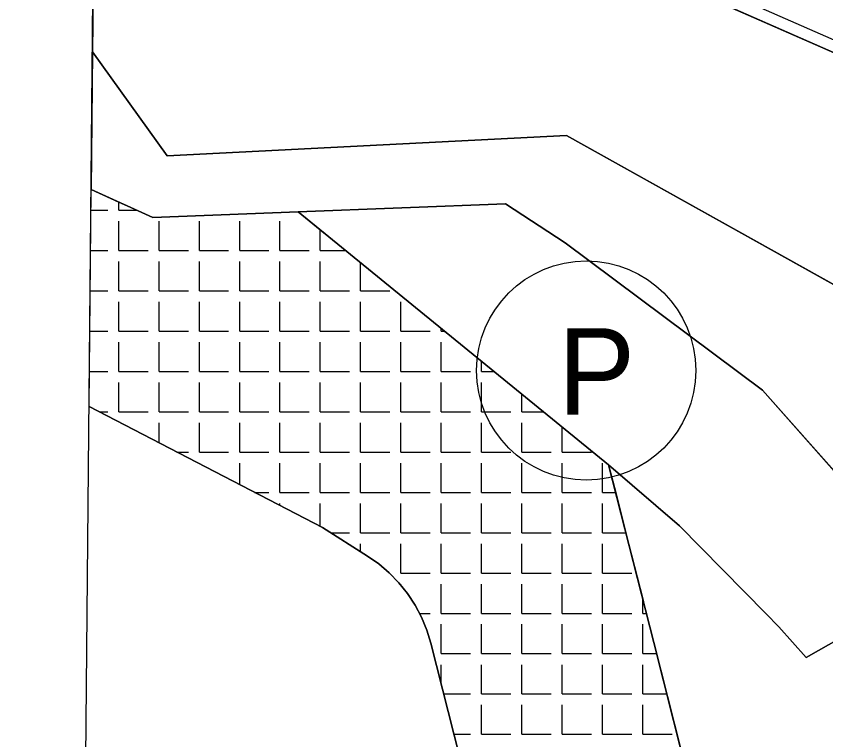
# Model space of a CAD drawing. Extents: x 427903 to 430077, y 4477233 to 4480385.
# Drawn here: x 427902.6 to 428042.9, y 4478521.2 to 4478646.6 of the extents above; entities that cross this region are included whole.
import ezdxf

# ---------------------------------------------------------------- set-up
doc = ezdxf.new("R2010")
doc.units = 0
for name, color, linetype in [('ADA', 7, 'Continuous'), ('ADAKENARI', 7, 'Continuous'), ('KALDIRIM', 7, 'Continuous'), ('KIYI', 7, 'Continuous'), ('KIYIKENARCIZGI', 7, 'Continuous'), ('LJ_SEMBOL', 7, 'Continuous'), ('PL_AYA_PARK_DINLENME', 7, 'Continuous'), ('PL_DOLGU', 7, 'Continuous'), ('PL_K_TALI_IS_MRK', 7, 'Continuous'), ('PL_KON_MEV_350', 7, 'Continuous'), ('PL_TA_K_OTOPARK', 7, 'Continuous'), ('SıNıR', 7, 'Continuous'), ('TR_KIYI', 7, 'Continuous'), ('TR_ORTAYOGUNKONUT', 7, 'Continuous'), ('TR_TALIISMERK', 7, 'Continuous')]:
    doc.layers.add(name, color=color, linetype=linetype)

msp = doc.modelspace()

# ---------------------------------------------------------------- linework, layer by layer
at = {"layer": 'ADA'}
msp.add_lwpolyline([(428005.26, 4478568.85), (428017.53, 4478558.25), (428032.49, 4478543.09), (428034.75, 4478540.79), (428039.48, 4478535.47), (428059.64, 4478546.89)], dxfattribs=at)
at = {"layer": 'ADAKENARI'}
for p, q in [((427945.65, 4478683.57), (428091.19, 4478619.67)), ((427915.79, 4478640.39), (427928.72, 4478622.38)), ((427928.72, 4478622.38), (427997.98, 4478625.89)), ((427997.98, 4478625.89), (428051.01, 4478596.31)), ((427926.24, 4478611.7), (427915.56, 4478616.56)), ((427987.4, 4478614.09), (427951.44, 4478612.68)), ((427997.71, 4478607.32), (427987.4, 4478614.09)), ((427951.44, 4478612.68), (427926.24, 4478611.7)), ((428031.92, 4478581.8), (427997.71, 4478607.32)), ((428048.79, 4478562.75), (428031.92, 4478581.8))]:
    msp.add_line(p, q, dxfattribs=at)
at = {"layer": 'KALDIRIM'}
msp.add_line((428092, 4478621.5), (427946.46, 4478685.4), dxfattribs=at)
at = {"layer": 'KIYI'}
for p, q in [((427915.2, 4478578.93), (427955.66, 4478557.97)), ((427955.66, 4478557.97), (427963.47, 4478553.04)), ((427963.47, 4478553.04), (427965.43, 4478551.67)), ((427965.43, 4478551.67), (427967.24, 4478550.12)), ((427967.24, 4478550.12), (427968.91, 4478548.4)), ((427968.91, 4478548.4), (427970.4, 4478546.54)), ((427970.4, 4478546.54), (427971.71, 4478544.54)), ((427971.71, 4478544.54), (427972.82, 4478542.43)), ((427972.82, 4478542.43), (427973.73, 4478540.22)), ((427973.73, 4478540.22), (427974.43, 4478537.94)), ((427974.43, 4478537.94), (427979.44, 4478518.13))]:
    msp.add_line(p, q, dxfattribs=at)
at = {"layer": 'KIYIKENARCIZGI'}
for p, q in [((428005.26, 4478568.85), (427951.44, 4478612.68)), ((428013.08, 4478538.04), (428005.26, 4478568.85)), ((428022.63, 4478500.39), (428013.08, 4478538.04))]:
    msp.add_line(p, q, dxfattribs=at)
at = {"layer": 'LJ_SEMBOL'}
msp.add_circle((428001.38, 4478585.19), 19, dxfattribs=at)
at = {"layer": 'PL_AYA_PARK_DINLENME'}
msp.add_lwpolyline([(428114.25, 4478313.51), (428064.87, 4478539.25), (428059.64, 4478546.89), (428039.48, 4478535.47), (428034.75, 4478540.79), (428032.49, 4478543.09), (428017.53, 4478558.25), (428005.26, 4478568.85), (428006.48, 4478564.07), (428008.25, 4478557.08), (428011.16, 4478545.62), (428011.79, 4478543.11), (428013.08, 4478538.04), (428013.56, 4478536.13), (428015.34, 4478529.14), (428018.14, 4478518.08)], dxfattribs=at)
at = {"layer": 'PL_DOLGU'}
for points in [[(427915.2, 4478578.93), (427915.56, 4478616.56)], [(427915.2, 4478578.93), (427915.56, 4478616.56)], [(427915.56, 4478616.56), (427926.24, 4478611.7), (427951.44, 4478612.68), (428005.26, 4478568.85), (428013.08, 4478538.04), (428022.63, 4478500.39), (428030.78, 4478471), (428043.19, 4478419.02), (428062.79, 4478335.7), (428065.05, 4478326.22), (428070.28, 4478297.7), (428077.59, 4478258.73), (428080.14, 4478238.03), (428083.58, 4478195.5), (428087.15, 4478152.17), (428090.62, 4478147.29), (428105.66, 4478126.11), (428131.83, 4478090.59), (428146.88, 4478022.13), (428153.28, 4477995.07), (428160.32, 4477964.05), (428161.5, 4477959.01), (428182.61, 4477892.78)], [(427915.56, 4478616.56), (427926.24, 4478611.7), (427951.44, 4478612.68), (428005.26, 4478568.85), (428013.08, 4478538.04), (428022.63, 4478500.39), (428030.78, 4478471), (428043.19, 4478419.02), (428062.79, 4478335.7), (428065.05, 4478326.22), (428070.28, 4478297.7), (428077.59, 4478258.73), (428080.14, 4478238.03), (428083.58, 4478195.5), (428087.15, 4478152.17), (428090.62, 4478147.29), (428105.66, 4478126.11), (428131.83, 4478090.59), (428146.88, 4478022.13), (428153.28, 4477995.07), (428160.32, 4477964.05), (428161.5, 4477959.01), (428182.61, 4477892.78)], [(427979.44, 4478518.13), (427974.43, 4478537.94), (427973.73, 4478540.22), (427972.82, 4478542.43), (427971.71, 4478544.54), (427970.4, 4478546.54), (427968.91, 4478548.4), (427967.24, 4478550.12), (427965.43, 4478551.67), (427963.47, 4478553.04), (427955.66, 4478557.97), (427915.2, 4478578.93)], [(427979.44, 4478518.13), (427974.43, 4478537.94), (427973.73, 4478540.22), (427972.82, 4478542.43), (427971.71, 4478544.54), (427970.4, 4478546.54), (427968.91, 4478548.4), (427967.24, 4478550.12), (427965.43, 4478551.67), (427963.47, 4478553.04), (427955.66, 4478557.97), (427915.2, 4478578.93)]]:
    msp.add_lwpolyline(points, dxfattribs=at)
at = {"layer": 'PL_K_TALI_IS_MRK'}
for points in [[(427915.79, 4478640.39), (427915.56, 4478616.56)], [(427920.35, 4478614.38), (427923.47, 4478612.96), (427926.24, 4478611.7), (427951.44, 4478612.68), (427987.4, 4478614.09), (427997.71, 4478607.32), (428031.92, 4478581.8), (428048.79, 4478562.75), (428050.54, 4478560.19), (428080.55, 4478566.83), (428080.72, 4478566.87), (428051.01, 4478596.31), (427997.98, 4478625.89), (427928.72, 4478622.38), (427915.79, 4478640.39)], [(427915.56, 4478616.56), (427920.35, 4478614.38)]]:
    msp.add_lwpolyline(points, dxfattribs=at)
at = {"layer": 'PL_KON_MEV_350'}
for points in [[(428091.19, 4478619.67), (427945.65, 4478683.57)], [(427915.89, 4478650.76), (427915.79, 4478640.39)], [(427915.79, 4478640.39), (427928.72, 4478622.38), (427997.98, 4478625.89), (428051.01, 4478596.31), (428080.72, 4478566.87)]]:
    msp.add_lwpolyline(points, dxfattribs=at)
at = {"layer": 'PL_TA_K_OTOPARK'}
msp.add_lwpolyline([(428059.64, 4478546.89), (428048.79, 4478562.75), (428031.92, 4478581.8), (427997.71, 4478607.32), (427987.4, 4478614.09), (427951.44, 4478612.68), (427955.28, 4478609.56), (427959.68, 4478605.98), (427962.26, 4478603.87), (427976.23, 4478592.5), (427976.83, 4478592.01), (427983.22, 4478586.81), (427985.41, 4478585.02), (427990.2, 4478581.12), (427993.99, 4478578.04), (427997.19, 4478575.43), (428005.26, 4478568.85), (428017.53, 4478558.25), (428032.49, 4478543.09), (428034.75, 4478540.79), (428039.48, 4478535.47), (428059.64, 4478546.89)], dxfattribs=at)
at = {"layer": 'SıNıR'}
msp.add_line((427902.58, 4477253.75), (427929.02, 4480028.95), dxfattribs=at)
at = {"layer": 'TR_KIYI'}
for p, q in [((427920.35, 4478612.96), (427920.35, 4478614.38)), ((427920.35, 4478612.96), (427920.35, 4478614.38)), ((427915.53, 4478612.96), (427918.45, 4478612.96)), ((427920.35, 4478612.96), (427923.47, 4478612.96)), ((427920.35, 4478605.98), (427920.35, 4478611.06)), ((427920.35, 4478605.98), (427920.35, 4478611.06)), ((427927.34, 4478605.98), (427927.34, 4478611.06)), ((427927.34, 4478605.98), (427927.34, 4478611.06)), ((427934.32, 4478605.98), (427934.32, 4478611.06)), ((427934.32, 4478605.98), (427934.32, 4478611.06)), ((427941.31, 4478605.98), (427941.31, 4478611.06)), ((427941.31, 4478605.98), (427941.31, 4478611.06)), ((427948.29, 4478605.98), (427948.29, 4478611.06)), ((427955.28, 4478605.98), (427955.28, 4478609.56)), ((427915.46, 4478605.98), (427918.45, 4478605.98)), ((427920.35, 4478605.98), (427925.43, 4478605.98)), ((427927.34, 4478605.98), (427932.42, 4478605.98)), ((427934.32, 4478605.98), (427939.4, 4478605.98)), ((427941.31, 4478605.98), (427946.39, 4478605.98)), ((427948.29, 4478605.98), (427953.37, 4478605.98)), ((427955.28, 4478605.98), (427959.68, 4478605.98)), ((427920.35, 4478598.99), (427920.35, 4478604.07)), ((427920.35, 4478598.99), (427920.35, 4478604.07)), ((427927.34, 4478598.99), (427927.34, 4478604.07)), ((427927.34, 4478598.99), (427927.34, 4478604.07)), ((427934.32, 4478598.99), (427934.32, 4478604.07)), ((427934.32, 4478598.99), (427934.32, 4478604.07)), ((427941.31, 4478598.99), (427941.31, 4478604.07)), ((427941.31, 4478598.99), (427941.31, 4478604.07)), ((427948.29, 4478598.99), (427948.29, 4478604.07)), ((427955.28, 4478598.99), (427955.28, 4478604.07)), ((427962.26, 4478598.99), (427962.26, 4478603.87)), ((427915.39, 4478598.99), (427918.45, 4478598.99)), ((427920.35, 4478598.99), (427925.43, 4478598.99)), ((427927.34, 4478598.99), (427932.42, 4478598.99)), ((427934.32, 4478598.99), (427939.4, 4478598.99)), ((427941.31, 4478598.99), (427946.39, 4478598.99)), ((427948.29, 4478598.99), (427953.37, 4478598.99)), ((427955.28, 4478598.99), (427960.36, 4478598.99)), ((427962.26, 4478598.99), (427967.34, 4478598.99)), ((427920.35, 4478592.01), (427920.35, 4478597.09)), ((427920.35, 4478592.01), (427920.35, 4478597.09)), ((427927.34, 4478592.01), (427927.34, 4478597.09)), ((427927.34, 4478592.01), (427927.34, 4478597.09)), ((427934.32, 4478592.01), (427934.32, 4478597.09)), ((427934.32, 4478592.01), (427934.32, 4478597.09)), ((427941.31, 4478592.01), (427941.31, 4478597.09)), ((427941.31, 4478592.01), (427941.31, 4478597.09)), ((427948.29, 4478592.01), (427948.29, 4478597.09)), ((427955.28, 4478592.01), (427955.28, 4478597.09)), ((427962.26, 4478592.01), (427962.26, 4478597.09)), ((427969.25, 4478592.01), (427969.25, 4478597.09)), ((427915.33, 4478592.01), (427918.45, 4478592.01)), ((427920.35, 4478592.01), (427925.43, 4478592.01)), ((427927.34, 4478592.01), (427932.42, 4478592.01)), ((427934.32, 4478592.01), (427939.4, 4478592.01)), ((427941.31, 4478592.01), (427946.39, 4478592.01)), ((427948.29, 4478592.01), (427953.37, 4478592.01)), ((427955.28, 4478592.01), (427960.36, 4478592.01)), ((427962.26, 4478592.01), (427967.34, 4478592.01)), ((427969.25, 4478592.01), (427974.33, 4478592.01)), ((427976.23, 4478592.01), (427976.23, 4478592.5)), ((427976.23, 4478592.01), (427976.83, 4478592.01)), ((427920.35, 4478585.02), (427920.35, 4478590.1)), ((427920.35, 4478585.02), (427920.35, 4478590.1)), ((427927.34, 4478585.02), (427927.34, 4478590.1)), ((427927.34, 4478585.02), (427927.34, 4478590.1)), ((427934.32, 4478585.02), (427934.32, 4478590.1)), ((427934.32, 4478585.02), (427934.32, 4478590.1)), ((427941.31, 4478585.02), (427941.31, 4478590.1)), ((427941.31, 4478585.02), (427941.31, 4478590.1)), ((427948.29, 4478585.02), (427948.29, 4478590.1)), ((427955.28, 4478585.02), (427955.28, 4478590.1)), ((427962.26, 4478585.02), (427962.26, 4478590.1)), ((427969.25, 4478585.02), (427969.25, 4478590.1)), ((427976.23, 4478585.02), (427976.23, 4478590.1)), ((427983.22, 4478585.02), (427983.22, 4478586.81)), ((427983.22, 4478585.02), (427983.22, 4478586.81)), ((427915.26, 4478585.02), (427918.45, 4478585.02)), ((427920.35, 4478585.02), (427925.43, 4478585.02)), ((427927.34, 4478585.02), (427932.42, 4478585.02)), ((427934.32, 4478585.02), (427939.4, 4478585.02)), ((427941.31, 4478585.02), (427946.39, 4478585.02)), ((427948.29, 4478585.02), (427953.37, 4478585.02)), ((427955.28, 4478585.02), (427960.36, 4478585.02)), ((427962.26, 4478585.02), (427967.34, 4478585.02)), ((427969.25, 4478585.02), (427974.33, 4478585.02)), ((427976.23, 4478585.02), (427981.31, 4478585.02)), ((427983.22, 4478585.02), (427985.41, 4478585.02)), ((427920.35, 4478578.04), (427920.35, 4478583.12)), ((427920.35, 4478578.04), (427920.35, 4478583.12)), ((427927.34, 4478578.04), (427927.34, 4478583.12)), ((427927.34, 4478578.04), (427927.34, 4478583.12)), ((427934.32, 4478578.04), (427934.32, 4478583.12)), ((427934.32, 4478578.04), (427934.32, 4478583.12)), ((427941.31, 4478578.04), (427941.31, 4478583.12)), ((427941.31, 4478578.04), (427941.31, 4478583.12)), ((427948.29, 4478578.04), (427948.29, 4478583.12)), ((427955.28, 4478578.04), (427955.28, 4478583.12)), ((427962.26, 4478578.04), (427962.26, 4478583.12)), ((427969.25, 4478578.04), (427969.25, 4478583.12)), ((427976.23, 4478578.04), (427976.23, 4478583.12)), ((427983.22, 4478578.04), (427983.22, 4478583.12)), ((427983.22, 4478578.04), (427983.22, 4478583.12)), ((427990.2, 4478578.04), (427990.2, 4478581.12)), ((427990.2, 4478578.04), (427990.2, 4478581.12)), ((427916.93, 4478578.04), (427918.45, 4478578.04)), ((427920.35, 4478578.04), (427925.43, 4478578.04)), ((427927.34, 4478578.04), (427932.42, 4478578.04)), ((427934.32, 4478578.04), (427939.4, 4478578.04)), ((427941.31, 4478578.04), (427946.39, 4478578.04)), ((427948.29, 4478578.04), (427953.37, 4478578.04)), ((427955.28, 4478578.04), (427960.36, 4478578.04)), ((427962.26, 4478578.04), (427967.34, 4478578.04)), ((427969.25, 4478578.04), (427974.33, 4478578.04)), ((427976.23, 4478578.04), (427981.31, 4478578.04)), ((427983.22, 4478578.04), (427988.3, 4478578.04)), ((427990.2, 4478578.04), (427993.99, 4478578.04)), ((427927.34, 4478572.64), (427927.34, 4478576.13)), ((427927.34, 4478572.64), (427927.34, 4478576.13)), ((427934.32, 4478571.05), (427934.32, 4478576.13)), ((427934.32, 4478571.05), (427934.32, 4478576.13)), ((427941.31, 4478571.05), (427941.31, 4478576.13)), ((427941.31, 4478571.05), (427941.31, 4478576.13)), ((427948.29, 4478571.05), (427948.29, 4478576.13)), ((427955.28, 4478571.05), (427955.28, 4478576.13)), ((427962.26, 4478571.05), (427962.26, 4478576.13)), ((427969.25, 4478571.05), (427969.25, 4478576.13)), ((427976.23, 4478571.05), (427976.23, 4478576.13)), ((427983.22, 4478571.05), (427983.22, 4478576.13)), ((427983.22, 4478571.05), (427983.22, 4478576.13)), ((427990.2, 4478571.05), (427990.2, 4478576.13)), ((427990.2, 4478571.05), (427990.2, 4478576.13)), ((427997.19, 4478571.05), (427997.19, 4478575.43)), ((427997.19, 4478571.05), (427997.19, 4478575.43)), ((427930.41, 4478571.05), (427932.42, 4478571.05)), ((427934.32, 4478571.05), (427939.4, 4478571.05)), ((427941.31, 4478571.05), (427946.39, 4478571.05)), ((427948.29, 4478571.05), (427953.37, 4478571.05)), ((427955.28, 4478571.05), (427960.36, 4478571.05)), ((427962.26, 4478571.05), (427967.34, 4478571.05)), ((427969.25, 4478571.05), (427974.33, 4478571.05)), ((427976.23, 4478571.05), (427981.31, 4478571.05)), ((427983.22, 4478571.05), (427988.3, 4478571.05)), ((427990.2, 4478571.05), (427995.28, 4478571.05)), ((427997.19, 4478571.05), (428002.27, 4478571.05)), ((427934.32, 4478569.03), (427934.32, 4478569.15)), ((427934.32, 4478569.03), (427934.32, 4478569.15)), ((427941.31, 4478565.41), (427941.31, 4478569.15)), ((427941.31, 4478565.41), (427941.31, 4478569.15)), ((427948.29, 4478564.07), (427948.29, 4478569.15)), ((427955.28, 4478564.07), (427955.28, 4478569.15)), ((427962.26, 4478564.07), (427962.26, 4478569.15)), ((427969.25, 4478564.07), (427969.25, 4478569.15)), ((427976.23, 4478564.07), (427976.23, 4478569.15)), ((427983.22, 4478564.07), (427983.22, 4478569.15)), ((427983.22, 4478564.07), (427983.22, 4478569.15)), ((427990.2, 4478564.07), (427990.2, 4478569.15)), ((427990.2, 4478564.07), (427990.2, 4478569.15)), ((427997.19, 4478564.07), (427997.19, 4478569.15)), ((427997.19, 4478564.07), (427997.19, 4478569.15)), ((428004.17, 4478564.07), (428004.17, 4478569.15)), ((428004.17, 4478564.07), (428004.17, 4478569.15)), ((427943.9, 4478564.07), (427946.39, 4478564.07)), ((427948.29, 4478564.07), (427953.37, 4478564.07)), ((427955.28, 4478564.07), (427960.36, 4478564.07)), ((427962.26, 4478564.07), (427967.34, 4478564.07)), ((427969.25, 4478564.07), (427974.33, 4478564.07)), ((427976.23, 4478564.07), (427981.31, 4478564.07)), ((427983.22, 4478564.07), (427988.3, 4478564.07)), ((427990.2, 4478564.07), (427995.28, 4478564.07)), ((427997.19, 4478564.07), (428002.27, 4478564.07)), ((428004.17, 4478564.07), (428006.48, 4478564.07)), ((427948.29, 4478561.79), (427948.29, 4478562.16)), ((427955.28, 4478558.17), (427955.28, 4478562.16)), ((427962.26, 4478557.08), (427962.26, 4478562.16)), ((427969.25, 4478557.08), (427969.25, 4478562.16)), ((427976.23, 4478557.08), (427976.23, 4478562.16)), ((427983.22, 4478557.08), (427983.22, 4478562.16)), ((427983.22, 4478557.08), (427983.22, 4478562.16)), ((427990.2, 4478557.08), (427990.2, 4478562.16)), ((427990.2, 4478557.08), (427990.2, 4478562.16)), ((427997.19, 4478557.08), (427997.19, 4478562.16)), ((427997.19, 4478557.08), (427997.19, 4478562.16)), ((428004.17, 4478557.08), (428004.17, 4478562.16)), ((428004.17, 4478557.08), (428004.17, 4478562.16)), ((427957.07, 4478557.08), (427960.36, 4478557.08)), ((427962.26, 4478557.08), (427967.34, 4478557.08)), ((427969.25, 4478557.08), (427974.33, 4478557.08)), ((427976.23, 4478557.08), (427981.31, 4478557.08)), ((427983.22, 4478557.08), (427988.3, 4478557.08)), ((427990.2, 4478557.08), (427995.28, 4478557.08)), ((427997.19, 4478557.08), (428002.27, 4478557.08)), ((428004.17, 4478557.08), (428008.25, 4478557.08)), ((427962.26, 4478553.8), (427962.26, 4478555.18)), ((427969.25, 4478550.1), (427969.25, 4478555.18)), ((427976.23, 4478550.1), (427976.23, 4478555.18)), ((427983.22, 4478550.1), (427983.22, 4478555.18)), ((427983.22, 4478550.1), (427983.22, 4478555.18)), ((427990.2, 4478550.1), (427990.2, 4478555.18)), ((427990.2, 4478550.1), (427990.2, 4478555.18)), ((427997.19, 4478550.1), (427997.19, 4478555.18)), ((427997.19, 4478550.1), (427997.19, 4478555.18)), ((428004.17, 4478550.1), (428004.17, 4478555.18)), ((428004.17, 4478550.1), (428004.17, 4478555.18)), ((427967.27, 4478550.1), (427967.34, 4478550.1)), ((427969.25, 4478550.1), (427974.33, 4478550.1)), ((427976.23, 4478550.1), (427981.31, 4478550.1)), ((427983.22, 4478550.1), (427988.3, 4478550.1)), ((427990.2, 4478550.1), (427995.28, 4478550.1)), ((427997.19, 4478550.1), (428002.27, 4478550.1)), ((428004.17, 4478550.1), (428009.25, 4478550.1)), ((427969.25, 4478547.98), (427969.25, 4478548.19)), ((427976.23, 4478543.11), (427976.23, 4478548.19)), ((427983.22, 4478543.11), (427983.22, 4478548.19)), ((427983.22, 4478543.11), (427983.22, 4478548.19)), ((427990.2, 4478543.11), (427990.2, 4478548.19)), ((427990.2, 4478543.11), (427990.2, 4478548.19)), ((427997.19, 4478543.11), (427997.19, 4478548.19)), ((427997.19, 4478543.11), (427997.19, 4478548.19)), ((428004.17, 4478543.11), (428004.17, 4478548.19)), ((428004.17, 4478543.11), (428004.17, 4478548.19)), ((428011.16, 4478543.11), (428011.16, 4478545.62)), ((428011.16, 4478543.11), (428011.16, 4478545.62)), ((427972.46, 4478543.11), (427974.33, 4478543.11)), ((427976.23, 4478543.11), (427981.31, 4478543.11)), ((427983.22, 4478543.11), (427988.3, 4478543.11)), ((427990.2, 4478543.11), (427995.28, 4478543.11)), ((427997.19, 4478543.11), (428002.27, 4478543.11)), ((428004.17, 4478543.11), (428009.25, 4478543.11)), ((428011.16, 4478543.11), (428011.79, 4478543.11)), ((427976.23, 4478536.13), (427976.23, 4478541.21)), ((427983.22, 4478536.13), (427983.22, 4478541.21)), ((427983.22, 4478536.13), (427983.22, 4478541.21)), ((427990.2, 4478536.13), (427990.2, 4478541.21)), ((427990.2, 4478536.13), (427990.2, 4478541.21)), ((427997.19, 4478536.13), (427997.19, 4478541.21)), ((427997.19, 4478536.13), (427997.19, 4478541.21)), ((428004.17, 4478536.13), (428004.17, 4478541.21)), ((428004.17, 4478536.13), (428004.17, 4478541.21)), ((428011.16, 4478536.13), (428011.16, 4478541.21)), ((428011.16, 4478536.13), (428011.16, 4478541.21)), ((427976.23, 4478536.13), (427981.31, 4478536.13)), ((427983.22, 4478536.13), (427988.3, 4478536.13)), ((427990.2, 4478536.13), (427995.28, 4478536.13)), ((427997.19, 4478536.13), (428002.27, 4478536.13)), ((428004.17, 4478536.13), (428009.25, 4478536.13)), ((428011.16, 4478536.13), (428013.56, 4478536.13)), ((427976.23, 4478530.8), (427976.23, 4478534.22)), ((427983.22, 4478529.14), (427983.22, 4478534.22)), ((427983.22, 4478529.14), (427983.22, 4478534.22)), ((427990.2, 4478529.14), (427990.2, 4478534.22)), ((427990.2, 4478529.14), (427990.2, 4478534.22)), ((427997.19, 4478529.14), (427997.19, 4478534.22)), ((427997.19, 4478529.14), (427997.19, 4478534.22)), ((428004.17, 4478529.14), (428004.17, 4478534.22)), ((428004.17, 4478529.14), (428004.17, 4478534.22)), ((428011.16, 4478529.14), (428011.16, 4478534.22)), ((428011.16, 4478529.14), (428011.16, 4478534.22)), ((427976.65, 4478529.14), (427981.31, 4478529.14)), ((427983.22, 4478529.14), (427988.3, 4478529.14)), ((427990.2, 4478529.14), (427995.28, 4478529.14)), ((427997.19, 4478529.14), (428002.27, 4478529.14)), ((428004.17, 4478529.14), (428009.25, 4478529.14)), ((428011.16, 4478529.14), (428015.34, 4478529.14)), ((427983.22, 4478522.16), (427983.22, 4478527.24)), ((427983.22, 4478522.16), (427983.22, 4478527.24)), ((427990.2, 4478522.16), (427990.2, 4478527.24)), ((427990.2, 4478522.16), (427990.2, 4478527.24)), ((427997.19, 4478522.16), (427997.19, 4478527.24)), ((427997.19, 4478522.16), (427997.19, 4478527.24)), ((428004.17, 4478522.16), (428004.17, 4478527.24)), ((428004.17, 4478522.16), (428004.17, 4478527.24)), ((428011.16, 4478522.16), (428011.16, 4478527.24)), ((428011.16, 4478522.16), (428011.16, 4478527.24)), ((427978.42, 4478522.16), (427981.31, 4478522.16)), ((427983.22, 4478522.16), (427988.3, 4478522.16)), ((427990.2, 4478522.16), (427995.28, 4478522.16)), ((427997.19, 4478522.16), (428002.27, 4478522.16)), ((428004.17, 4478522.16), (428009.25, 4478522.16)), ((428011.16, 4478522.16), (428016.24, 4478522.16))]:
    msp.add_line(p, q, dxfattribs=at)
at = {"layer": 'TR_ORTAYOGUNKONUT'}
for points in [[(428091.19, 4478619.67), (427945.65, 4478683.57)], [(427915.89, 4478650.76), (427915.79, 4478640.39)], [(427915.79, 4478640.39), (427928.72, 4478622.38), (427997.98, 4478625.89), (428051.01, 4478596.31)]]:
    msp.add_lwpolyline(points, dxfattribs=at)
at = {"layer": 'TR_TALIISMERK'}
for points in [[(427915.79, 4478640.39), (427915.56, 4478616.56)], [(427920.35, 4478614.38), (427923.47, 4478612.96), (427926.24, 4478611.7), (427951.44, 4478612.68), (427987.4, 4478614.09), (427997.71, 4478607.32), (428031.92, 4478581.8), (428048.79, 4478562.75), (428050.54, 4478560.19), (428080.55, 4478566.83), (428080.72, 4478566.87), (428051.01, 4478596.31), (427997.98, 4478625.89), (427928.72, 4478622.38), (427915.79, 4478640.39)], [(427915.56, 4478616.56), (427920.35, 4478614.38)]]:
    msp.add_lwpolyline(points, dxfattribs=at)

# ---------------------------------------------------------------- texts
at = {"layer": 'LJ_SEMBOL'}
msp.add_text('P', height=15, dxfattribs=at).set_placement((427996.47, 4478577.52))

doc.saveas('drawing.dxf')
